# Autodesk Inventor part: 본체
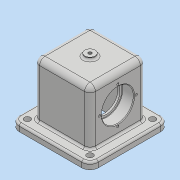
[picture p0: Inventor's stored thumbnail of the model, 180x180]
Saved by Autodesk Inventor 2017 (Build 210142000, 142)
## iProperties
Part Number: 본체
Material: 일반
Document SubType Name: Modeling
Designer: MRC
Density: 1 g/cm^3
Appearance: 기본값
Author: MRC
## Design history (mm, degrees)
sketch "스케치1"
  geometry: L1 (-58, 58)-(58, 58); L2 (58, 58)-(58, -58); L3 (58, -58)-(-58, -58); L4 (-58, -58)-(-58, 58); L5 (-58, 58)-(58, -58); L6 (58, 58)-(-58, -58); 1 further point
  constraints: 12 end point, 2 midpoint, 2 parallel, 1 horizontal, 1 perpendicular
  dimensions: "d0" = 116 distance between parallel lines of L3 L1; "d1" = 116 distance between parallel lines of L2 L4
extrude "돌출1" new body sketch "스케치1" distance "d2" = 10; taper "d3" = 0 deg
sketch "스케치2"
  geometry: L1 (-41, 41)-(41, 41); L2 (41, 41)-(41, -41); L3 (41, -41)-(-41, -41); L4 (-41, -41)-(-41, 41); L5 (-41, 41)-(41, -41); L6 (41, 41)-(-41, -41); 1 further point
  constraints: 12 end point, 2 midpoint, 2 parallel, 1 horizontal, 1 perpendicular
  dimensions: "d4" = 82 distance of L2.end L3.end; "d5" = 82 distance of L1.end L2.end
extrude "돌출2" join sketch "스케치2" distance "d6" = 80; taper "d7" = 0 deg
sketch "스케치3"
  geometry: L1 (-21, 30)-(21, 30); L2 (21, 30)-(21, -30); L3 (21, -30)-(-21, -30); L4 (-21, -30)-(-21, 30); L5 (-21, 30)-(21, -30); L6 (21, 30)-(-21, -30); 3 further points
  constraints: 12 end point, 3 midpoint, 2 parallel, 1 coincident, 1 horizontal, 1 perpendicular
  dimensions: "d8" = 60 distance between parallel lines of L3 L1; "d9" = 42 distance between parallel lines of L4 L2
extrude "돌출3" cut sketch "스케치3" distance "d10" = 80; taper "d11" = 0 deg
sketch "스케치4"
  geometry: L1 (10, 41)-(-38, 41); C1 r 23.5 at (-38, 41)
  constraints: 2 end point, 1 centre point, 1 coincident, 1 horizontal
  dimensions: "d12" = 47 diameter of C1; "d13" = 48 distance of L1.start L1.end
extrude "돌출4" cut sketch "스케치4" distance "d14" = 17; taper "d15" = 0 deg
sketch "스케치5"
  geometry: C1 r 20 at (0, 0); C2 r 23.5 at (0, 0) reference; 1 further point
  constraints: 1 centre point, 1 concentric
  dimensions: "d16" = 40 diameter of C1
extrude "돌출5" cut sketch "스케치5" distance "d17" = 10; taper "d18" = 0 deg
sketch "스케치6"
  geometry: L1 (-65, 41)-(-11, 41); C1 r 23.5 at (-38, 41) reference; A1 r 27 centre (-38, 41) between (-65, 41) and (-11, 41); 2 further points
  constraints: 3 point on circle, 2 end point, 1 centre point, 1 concentric, 1 horizontal, 1 midpoint, 1 point on line
  dimensions: "d19" = 54 diameter of A1
hole "구멍1" sketch "스케치6" at (-65, 41) diameter "d20" = 3.242; stored, may be unused: countersink angle "d24" = 90 deg, drill point angle "d26" = 118 deg; dims "d21" = 8, "d22" = 4, "d23" = 2, "d25" = 10
sketch "스케치7"
  geometry: C1 r 7.5 at (0, 0); 1 further point
  constraints: 1 centre point, 1 coincident
  dimensions: "d30" = 15 diameter of C1
extrude "돌출6" join sketch "스케치7" distance "d31" = 4; taper "d32" = 0 deg
sketch "스케치8"
  geometry: 2 further points
  constraints: 1 coincident
hole "구멍2" sketch "스케치8" at (0, 0) diameter "d33" = 4.917; stored, may be unused: countersink angle "d37" = 90 deg, drill point angle "d39" = 0 deg; dims "d34" = 14, "d35" = 4, "d36" = 2, "d38" = 14
fillet "모깎기1" dims "d40" = 0.6
chamfer "모따기1" distance "d41" = 1; stored, may be unused: second distance "d42" = 2, angle "d43" = 45 deg
fillet "모깎기2" dims "d44" = 8
sketch "스케치9"
  geometry: L1 (-58, 58)-(-58, -58) reference; L2 (58, 58)-(-58, 58) reference; C1 r 4.5 at (-46, 46); 1 further point
  constraints: 1 centre point
  dimensions: "d45" = 9 diameter of C1; "d46" = 12 distance from line of L1 C1.centre; "d47" = 12 distance from line of C1.centre L2
extrude "돌출7" cut sketch "스케치9" distance "d48" = 10; taper "d49" = 0 deg
fillet "모깎기3" dims "d56" = 12
fillet "모깎기4" dims "d57" = 3
fillet "모깎기5" dims "d58" = 3
sketch "스케치10"
  geometry: L1 (-13, 82)-(79, 82) reference; L2 (33, 82)-(33, 34); 1 further point
  constraints: 2 end point, 1 coincident, 1 vertical, 1 other
  dimensions: "d59" = 48 distance of L2.start L2.end
feature "엠보싱1" sketch "스케치10" dims "d0" = 116, "d1" = 116, "d8" = 60, "d9" = 42, "d60" = 0.5, "d61" = 0
fillet "모깎기6" dims "d62" = 3
node "솔리드1"
pattern_circular "원형 패턴1" dims angle "d28" = 360 deg
mirror "미러1"
pattern_linear "직사각형 패턴1" dims "d52" = 92, "d55" = 92
